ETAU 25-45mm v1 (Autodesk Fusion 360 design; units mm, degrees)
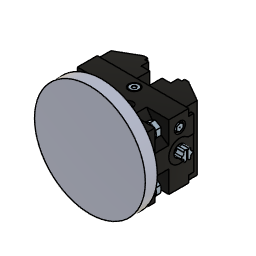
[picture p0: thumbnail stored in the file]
parameter "Ouverture" = 40
base_feature "Base Feature1" OffsetX 0 OffsetY 0 OffsetZ 0
base_feature "Base Feature1"
base_feature "Base Feature1"
position "Position1"
joint_origin "JointOrigin1" OffsetX 0 OffsetY 0 OffsetZ 0
joint_origin "JointOrigin1" OffsetX 0 OffsetY 0 OffsetZ 0
joint_origin "JointOrigin2" OffsetX 0 OffsetY 0 OffsetZ 0
joint "Assemble1" alignOffsetX 0 alignOffsetY 0 alignOffsetZ -6.7 (= "-Ouverture / 2 + 13.3 mm")
joint "Assemble2" alignOffsetX 0 alignOffsetY 0 alignOffsetZ 6.7 (= "Ouverture / 2 - 13.3 mm")
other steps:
create_component "CreateComponent1"
create_component "CreateComponent2"
create_component "CreateComponent3"
joint_origin "JointOrigin3" OffsetX 0 OffsetY 0 OffsetZ 0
